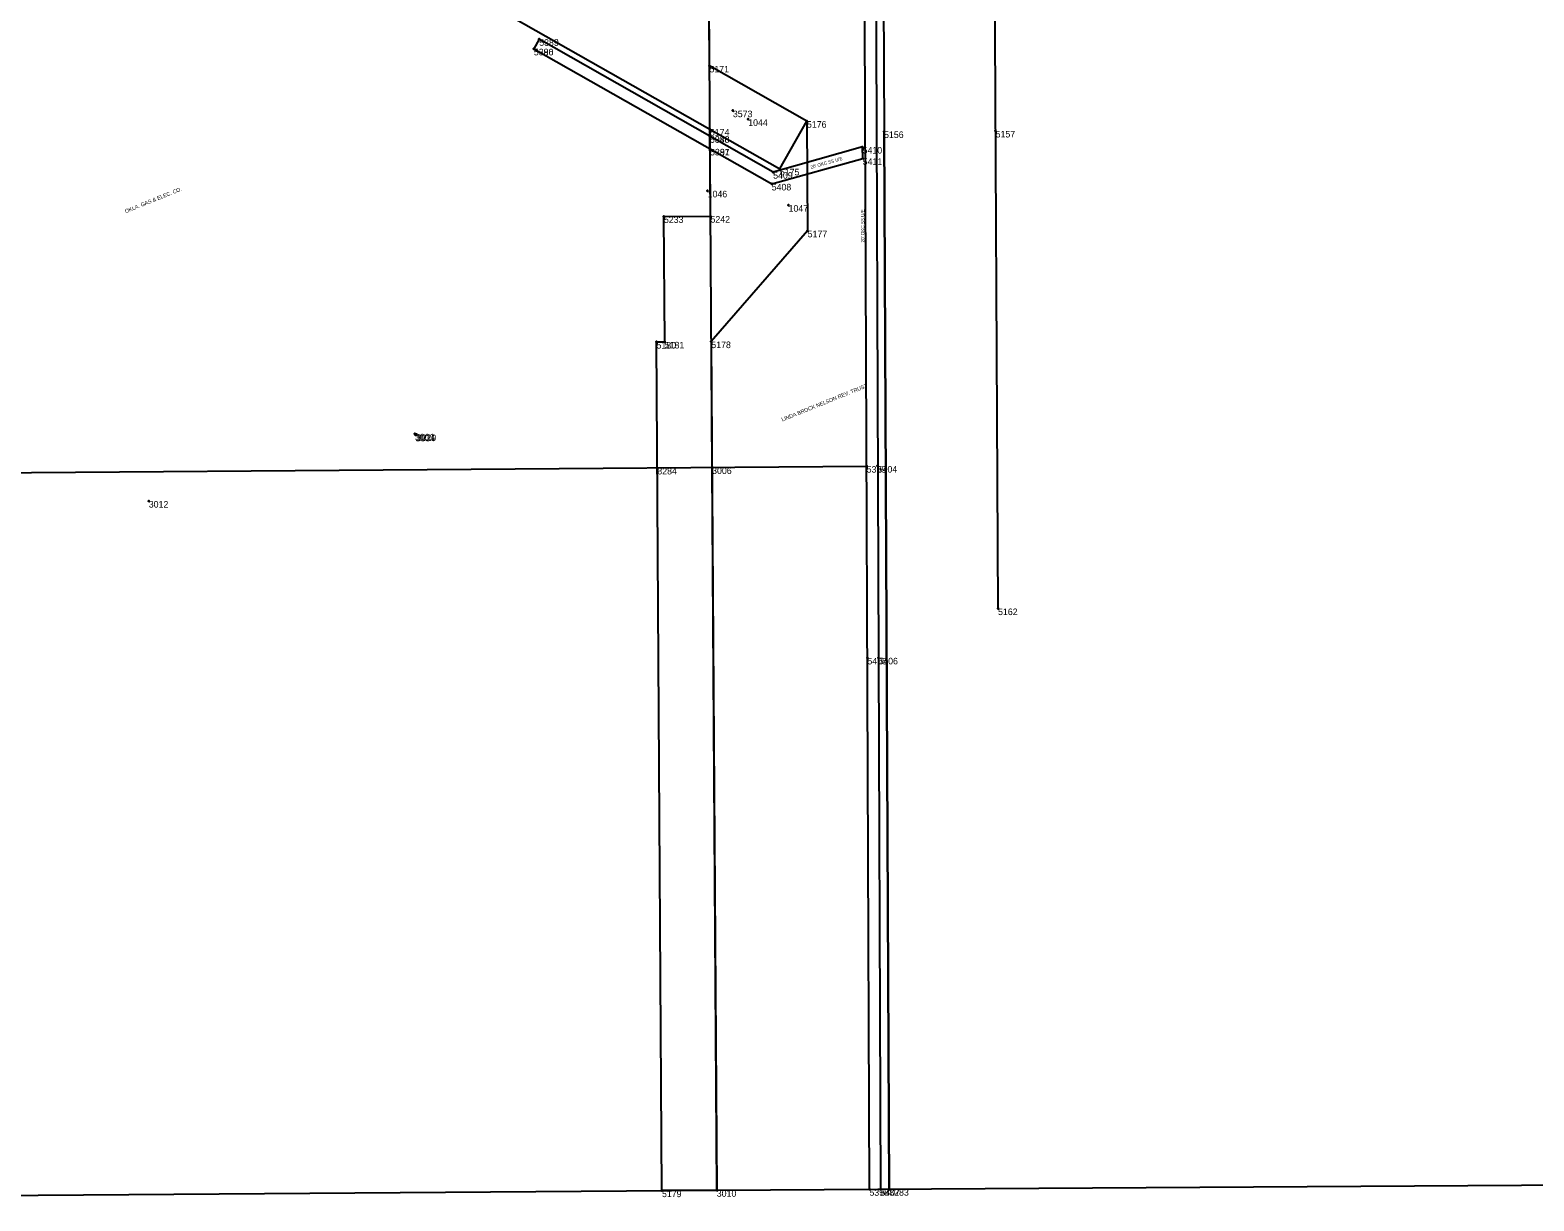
# Model space of a CAD drawing. Extents: x 2145146 to 2158053, y 137507 to 150829.
# Drawn here: x 2152334 to 2155078, y 140359 to 142495 of the extents above; entities that cross this region are included whole.
import ezdxf

# ---------------------------------------------------------------- set-up
doc = ezdxf.new("R2010")
doc.units = 0
for name, color, linetype in [('ALIGN_Cogo Points', 7, 'Continuous'), ('ALIGN_ROW Line', 7, 'Continuous'), ('PLSS_Easement', 7, 'Continuous'), ('PLSS_Property Line', 7, 'Continuous'), ('PLSS_Section Line', 7, 'Continuous'), ('PLSS_Text', 7, 'Continuous'), ('PLSS_Text_TURNED OFF', 7, 'Continuous')]:
    doc.layers.add(name, color=color, linetype=linetype)

msp = doc.modelspace()

# ---------------------------------------------------------------- linework, layer by layer
at = {"layer": 'ALIGN_Cogo Points'}
for points in [[(2153263.1, 142478.7), (2153263.1, 142479.9), (2153263.1, 142478.7), (2153261.9, 142478.7), (2153263.1, 142478.7), (2153263.1, 142477.5), (2153263.1, 142478.7), (2153264.3, 142478.7)], [(2153263.1, 142478.7), (2153263.1, 142479.9), (2153263.1, 142478.7), (2153261.9, 142478.7), (2153263.1, 142478.7), (2153263.1, 142477.5), (2153263.1, 142478.7), (2153264.3, 142478.7)], [(2153253.3, 142461.3), (2153253.3, 142462.5), (2153253.3, 142461.3), (2153252.1, 142461.3), (2153253.3, 142461.3), (2153253.3, 142460.1), (2153253.3, 142461.3), (2153254.5, 142461.3)], [(2153253.3, 142461.3), (2153253.3, 142462.5), (2153253.3, 142461.3), (2153252.1, 142461.3), (2153253.3, 142461.3), (2153253.3, 142460.1), (2153253.3, 142461.3), (2153254.5, 142461.3)], [(2153573.8, 142430.2), (2153573.8, 142431.4), (2153573.8, 142430.2), (2153572.6, 142430.2), (2153573.8, 142430.2), (2153573.8, 142429), (2153573.8, 142430.2), (2153575, 142430.2)], [(2153616.5, 142348.5), (2153616.5, 142349.7), (2153616.5, 142348.5), (2153615.3, 142348.5), (2153616.5, 142348.5), (2153616.5, 142347.3), (2153616.5, 142348.5), (2153617.7, 142348.5)], [(2153644.4, 142332.6), (2153644.4, 142333.8), (2153644.4, 142332.6), (2153643.2, 142332.6), (2153644.4, 142332.6), (2153644.4, 142331.4), (2153644.4, 142332.6), (2153645.6, 142332.6)], [(2153751.6, 142329.3), (2153751.6, 142330.5), (2153751.6, 142329.3), (2153750.4, 142329.3), (2153751.6, 142329.3), (2153751.6, 142328.1), (2153751.6, 142329.3), (2153752.8, 142329.3)], [(2153574.5, 142314.8), (2153574.5, 142316), (2153574.5, 142314.8), (2153573.3, 142314.8), (2153574.5, 142314.8), (2153574.5, 142313.6), (2153574.5, 142314.8), (2153575.7, 142314.8)], [(2153574.6, 142301.8), (2153574.6, 142303), (2153574.6, 142301.8), (2153573.4, 142301.8), (2153574.6, 142301.8), (2153574.6, 142300.6), (2153574.6, 142301.8), (2153575.8, 142301.8)], [(2153574.6, 142301.8), (2153574.6, 142303), (2153574.6, 142301.8), (2153573.4, 142301.8), (2153574.6, 142301.8), (2153574.6, 142300.6), (2153574.6, 142301.8), (2153575.8, 142301.8)], [(2153892.3, 142310.5), (2153892.3, 142311.7), (2153892.3, 142310.5), (2153891.1, 142310.5), (2153892.3, 142310.5), (2153892.3, 142309.3), (2153892.3, 142310.5), (2153893.5, 142310.5)], [(2154095.9, 142311.5), (2154095.9, 142312.7), (2154095.9, 142311.5), (2154094.7, 142311.5), (2154095.9, 142311.5), (2154095.9, 142310.3), (2154095.9, 142311.5), (2154097.1, 142311.5)], [(2153574.8, 142278.7), (2153574.8, 142279.9), (2153574.8, 142278.7), (2153573.6, 142278.7), (2153574.8, 142278.7), (2153574.8, 142277.5), (2153574.8, 142278.7), (2153576, 142278.7)], [(2153574.8, 142278.7), (2153574.8, 142279.9), (2153574.8, 142278.7), (2153573.6, 142278.7), (2153574.8, 142278.7), (2153574.8, 142277.5), (2153574.8, 142278.7), (2153576, 142278.7)], [(2153853.2, 142282.1), (2153853.2, 142283.3), (2153853.2, 142282.1), (2153852, 142282.1), (2153853.2, 142282.1), (2153853.2, 142280.9), (2153853.2, 142282.1), (2153854.4, 142282.1)], [(2153853.3, 142261.4), (2153853.3, 142262.6), (2153853.3, 142261.4), (2153852.1, 142261.4), (2153853.3, 142261.4), (2153853.3, 142260.2), (2153853.3, 142261.4), (2153854.5, 142261.4)], [(2153690, 142236.3), (2153690, 142237.5), (2153690, 142236.3), (2153688.8, 142236.3), (2153690, 142236.3), (2153690, 142235.1), (2153690, 142236.3), (2153691.2, 142236.3)], [(2153702.2, 142242.3), (2153702.2, 142243.5), (2153702.2, 142242.3), (2153701, 142242.3), (2153702.2, 142242.3), (2153702.2, 142241.1), (2153702.2, 142242.3), (2153703.4, 142242.3)], [(2153570.4, 142202.2), (2153570.4, 142203.4), (2153570.4, 142202.2), (2153569.2, 142202.2), (2153570.4, 142202.2), (2153570.4, 142201), (2153570.4, 142202.2), (2153571.6, 142202.2)], [(2153687.3, 142214.8), (2153687.3, 142216), (2153687.3, 142214.8), (2153686.1, 142214.8), (2153687.3, 142214.8), (2153687.3, 142213.6), (2153687.3, 142214.8), (2153688.5, 142214.8)], [(2153718.1, 142176.1), (2153718.1, 142177.3), (2153718.1, 142176.1), (2153716.9, 142176.1), (2153718.1, 142176.1), (2153718.1, 142174.9), (2153718.1, 142176.1), (2153719.3, 142176.1)], [(2153490.6, 142155.5), (2153490.6, 142156.7), (2153490.6, 142155.5), (2153489.4, 142155.5), (2153490.6, 142155.5), (2153490.6, 142154.3), (2153490.6, 142155.5), (2153491.8, 142155.5)], [(2153575.6, 142156.1), (2153575.6, 142157.3), (2153575.6, 142156.1), (2153574.4, 142156.1), (2153575.6, 142156.1), (2153575.6, 142154.9), (2153575.6, 142156.1), (2153576.8, 142156.1)], [(2153752.9, 142129.3), (2153752.9, 142130.5), (2153752.9, 142129.3), (2153751.7, 142129.3), (2153752.9, 142129.3), (2153752.9, 142128.1), (2153752.9, 142129.3), (2153754.1, 142129.3)], [(2153477.1, 141926.3), (2153477.1, 141927.5), (2153477.1, 141926.3), (2153475.9, 141926.3), (2153477.1, 141926.3), (2153477.1, 141925.1), (2153477.1, 141926.3), (2153478.3, 141926.3)], [(2153492.1, 141926.5), (2153492.1, 141927.7), (2153492.1, 141926.5), (2153490.9, 141926.5), (2153492.1, 141926.5), (2153492.1, 141925.3), (2153492.1, 141926.5), (2153493.3, 141926.5)], [(2153577.1, 141927.1), (2153577.1, 141928.3), (2153577.1, 141927.1), (2153575.9, 141927.1), (2153577.1, 141927.1), (2153577.1, 141925.9), (2153577.1, 141927.1), (2153578.3, 141927.1)], [(2153036.4, 141758.7), (2153036.4, 141759.9), (2153036.4, 141758.7), (2153035.2, 141758.7), (2153036.4, 141758.7), (2153036.4, 141757.5), (2153036.4, 141758.7), (2153037.6, 141758.7)], [(2153037.4, 141756.9), (2153037.4, 141758.1), (2153037.4, 141756.9), (2153036.2, 141756.9), (2153037.4, 141756.9), (2153037.4, 141755.7), (2153037.4, 141756.9), (2153038.6, 141756.9)], [(2153039.5, 141757.4), (2153039.5, 141758.6), (2153039.5, 141757.4), (2153038.3, 141757.4), (2153039.5, 141757.4), (2153039.5, 141756.2), (2153039.5, 141757.4), (2153040.7, 141757.4)], [(2153478.6, 141696.6), (2153478.6, 141697.8), (2153478.6, 141696.6), (2153477.4, 141696.6), (2153478.6, 141696.6), (2153478.6, 141695.4), (2153478.6, 141696.6), (2153479.8, 141696.6)], [(2153578.6, 141697.4), (2153578.6, 141698.6), (2153578.6, 141697.4), (2153577.4, 141697.4), (2153578.6, 141697.4), (2153578.6, 141696.2), (2153578.6, 141697.4), (2153579.8, 141697.4)], [(2153860.6, 141699.9), (2153860.6, 141701.1), (2153860.6, 141699.9), (2153859.4, 141699.9), (2153860.6, 141699.9), (2153860.6, 141698.7), (2153860.6, 141699.9), (2153861.8, 141699.9)], [(2153880.6, 141700), (2153880.6, 141701.2), (2153880.6, 141700), (2153879.4, 141700), (2153880.6, 141700), (2153880.6, 141698.8), (2153880.6, 141700), (2153881.8, 141700)], [(2152550.7, 141636.1), (2152550.7, 141637.3), (2152550.7, 141636.1), (2152549.5, 141636.1), (2152550.7, 141636.1), (2152550.7, 141634.9), (2152550.7, 141636.1), (2152551.9, 141636.1)], [(2154100.3, 141439.9), (2154100.3, 141441.1), (2154100.3, 141439.9), (2154099.1, 141439.9), (2154100.3, 141439.9), (2154100.3, 141438.7), (2154100.3, 141439.9), (2154101.5, 141439.9)], [(2153861.9, 141349.9), (2153861.9, 141351.1), (2153861.9, 141349.9), (2153860.7, 141349.9), (2153861.9, 141349.9), (2153861.9, 141348.7), (2153861.9, 141349.9), (2153863.1, 141349.9)], [(2153881.9, 141350), (2153881.9, 141351.2), (2153881.9, 141350), (2153880.7, 141350), (2153881.9, 141350), (2153881.9, 141348.8), (2153881.9, 141350), (2153883.1, 141350)], [(2153587.1, 140378.5), (2153587.1, 140379.7), (2153587.1, 140378.5), (2153585.9, 140378.5), (2153587.1, 140378.5), (2153587.1, 140377.3), (2153587.1, 140378.5), (2153588.3, 140378.5)], [(2153865.6, 140380.3), (2153865.6, 140381.5), (2153865.6, 140380.3), (2153864.4, 140380.3), (2153865.6, 140380.3), (2153865.6, 140379.1), (2153865.6, 140380.3), (2153866.8, 140380.3)], [(2153885.6, 140380.4), (2153885.6, 140381.6), (2153885.6, 140380.4), (2153884.4, 140380.4), (2153885.6, 140380.4), (2153885.6, 140379.2), (2153885.6, 140380.4), (2153886.8, 140380.4)], [(2153901.8, 140380.5), (2153901.8, 140381.7), (2153901.8, 140380.5), (2153900.6, 140380.5), (2153901.8, 140380.5), (2153901.8, 140379.3), (2153901.8, 140380.5), (2153903, 140380.5)], [(2153487.1, 140377.8), (2153487.1, 140379), (2153487.1, 140377.8), (2153485.9, 140377.8), (2153487.1, 140377.8), (2153487.1, 140376.6), (2153487.1, 140377.8), (2153488.3, 140377.8)]]:
    msp.add_lwpolyline(points, dxfattribs=at)
at = {"layer": 'ALIGN_ROW Line'}
for points in [[(2154100.3, 141439.9), (2154093.9, 142723), (2154315.7, 142724.5)], [(2153075.6, 142598.1), (2153075.6, 142598.1), (2153574.5, 142314.8), (2153702.2, 142242.3), (2153751.6, 142329.3), (2153573.8, 142430.2), (2153573, 142523.2), (2153673, 142523.9), (2153672, 142673.9), (2153890.5, 142675.5), (2153892.3, 142310.5), (2153901.8, 140380.5), (2153892.3, 142310.5)]]:
    msp.add_lwpolyline(points, dxfattribs=at)
msp.add_lwpolyline([(2153577.1, 141927.1), (2153587.1, 140378.5), (2153487.1, 140377.8), (2153477.1, 141926.3), (2153492.1, 141926.5), (2153490.6, 142155.5), (2153575.6, 142156.1), (2153574.5, 142314.8), (2153702.2, 142242.3), (2153751.6, 142329.3), (2153752.9, 142129.3)], close=True, dxfattribs=at)
at = {"layer": 'PLSS_Easement'}
msp.add_lwpolyline([(2153865.6, 140380.3), (2153856.9, 142658.3), (2153891.9, 142659.4), (2153892, 142639.4), (2153877, 142638.9), (2153885.6, 140380.4)], dxfattribs=at)
msp.add_lwpolyline([(2153263.1, 142478.7), (2153253.3, 142461.3), (2153687.3, 142214.8), (2153853.3, 142261.4), (2153853.2, 142282.1), (2153690, 142236.3)], close=True, dxfattribs=at)
at = {"layer": 'PLSS_Property Line'}
msp.add_lwpolyline([(2151794.6, 141684.3), (2152256.1, 141687.7), (2153860.6, 141699.9)], dxfattribs=at)
at = {"layer": 'PLSS_Section Line'}
for points in [[(2153587.1, 140378.5), (2153570, 143016.2)], [(2153587.1, 140378.5), (2156230.3, 140395.2)], [(2150945, 140358.9), (2153587.1, 140378.5)]]:
    msp.add_lwpolyline(points, dxfattribs=at)

# ---------------------------------------------------------------- texts
at = {"layer": 'ALIGN_Cogo Points'}
for s, p in [('5385', (2153263.1, 142466.7)), ('5389', (2153263.1, 142466.7)), ('5386', (2153253.3, 142449.3)), ('5390', (2153253.3, 142449.3)), ('5171', (2153573.8, 142418.2)), ('3573', (2153616.5, 142336.5)), ('1044', (2153644.4, 142320.6)), ('5176', (2153751.6, 142317.3)), ('5174', (2153574.5, 142302.8)), ('5046', (2153574.6, 142289.8)), ('5388', (2153574.6, 142289.8)), ('5156', (2153892.3, 142298.5)), ('5157', (2154095.9, 142299.5)), ('5387', (2153574.8, 142266.7)), ('5391', (2153574.8, 142266.7)), ('5410', (2153853.2, 142270.1)), ('5411', (2153853.3, 142249.4)), ('5409', (2153690, 142224.3)), ('5175', (2153702.2, 142230.3)), ('1046', (2153570.4, 142190.2)), ('5408', (2153687.3, 142202.8)), ('1047', (2153718.1, 142164.1)), ('5233', (2153490.6, 142143.5)), ('5242', (2153575.6, 142144.1)), ('5177', (2153752.9, 142117.3)), ('5180', (2153477.1, 141914.3)), ('5181', (2153492.1, 141914.5)), ('5178', (2153577.1, 141915.1)), ('3001', (2153036.4, 141746.7)), ('3034', (2153037.4, 141744.9)), ('3029', (2153039.5, 141745.4)), ('8284', (2153478.6, 141684.6)), ('3006', (2153578.6, 141685.4)), ('5399', (2153860.6, 141687.9)), ('5404', (2153880.6, 141688)), ('3012', (2152550.7, 141624.1)), ('5162', (2154100.3, 141427.9)), ('5405', (2153861.9, 141337.9)), ('5406', (2153881.9, 141338)), ('5398', (2153865.6, 140368.3)), ('5407', (2153885.6, 140368.4)), ('8283', (2153901.8, 140368.5)), ('5179', (2153487.1, 140365.8)), ('3010', (2153587.1, 140366.5))]:
    msp.add_text(s, height=12, dxfattribs=at).set_placement(p)
at = {"layer": 'PLSS_Text'}
for rotation, p in [(15.6909, (2153759, 142242.2)), (90, (2153856.3, 142107.9))]:
    msp.add_text("20' OKC SS U/E", height=6, rotation=rotation, dxfattribs=at).set_placement(p)
at = {"layer": 'PLSS_Text_TURNED OFF'}
for s, p in [('OKLA. GAS & ELEC. CO.', (2152508.7, 142161.2)), ('LINDA BROCK NELSON REV. TRUST', (2153706.8, 141781))]:
    msp.add_text(s, height=7, rotation=22, dxfattribs=at).set_placement(p)

doc.saveas('drawing.dxf')
